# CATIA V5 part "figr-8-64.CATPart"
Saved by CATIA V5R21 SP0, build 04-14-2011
Part number: Part1
Bounding box of the stored display mesh (mm): x -68.924 to 54.237, y -54.052 to 120.856, z 0 to 40
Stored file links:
  D:\CATIA V5R21 E-RESOURCES\CATIA-V5R21\catia-v5r21-prt\c08-catia-v5r20-prt\c08-catia-v5r21-figr-8-64.CATPart
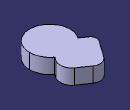
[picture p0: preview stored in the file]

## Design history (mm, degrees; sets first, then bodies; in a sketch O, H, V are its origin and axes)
Body1 (main body)
  Sketch1 on xy-plane, origin (0, 0, 0), H (1, 0, 0), V (0, 1, 0)
    circle A1 centre (0, 0) radius 54.2371
    point P1 (0, 54.2371)
    coincidence: A1 P1, P1 V
  Pad1: profile Sketch1, direction (0, 0, 1), length 40
  Body2
    Sketch2 on xy-plane, origin (0, 0, 0), H (1, 0, 0), V (0, 1, 0)
      line L1 (0, 0) -> (36.9865, 52.8223)
      arc A1 centre (11.6298, 70.5772) radius 30.9549 from (36.9865, 52.8223) to (29.3848, 95.934) ccw
      line L2 (29.3848, 95.934) -> (0.2008, 116.3688)
      arc A2 centre (-14.1853, 95.8234) radius 25.0814 from (0.2008, 116.3688) to (-34.7307, 110.2094) ccw
      line L3 (-34.7307, 110.2094) -> (-66.0893, 65.4248)
      arc A3 centre (-53.2403, 56.4279) radius 15.6856 from (-66.0893, 65.4248) to (-62.2373, 43.579) ccw
      line L4 (-62.2373, 43.579) -> (0, 0)
      tangency: A1 L1, L2 A1, A2 L2, L3 A2, A3 L3, L4 A3
    Pad2: profile Sketch2, direction (0, 0, 1), length 40
  Add1: tool Body2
